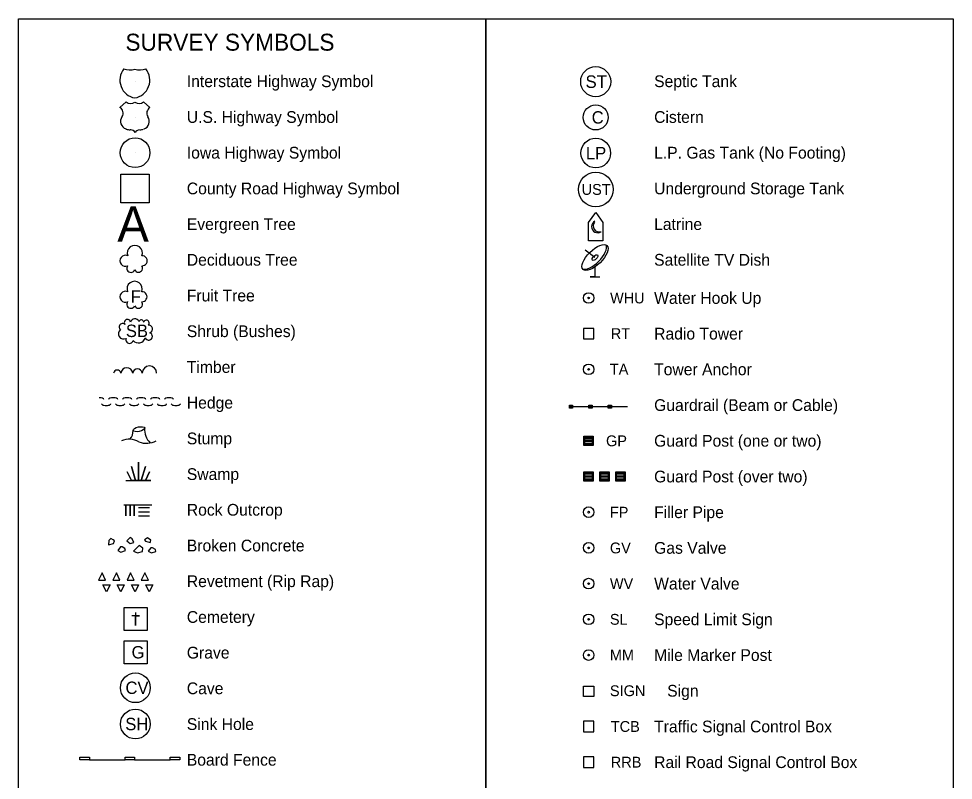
# Model space of a CAD drawing. Extents: x 6082259 to 6083454, y 5964102 to 5966092.
# Drawn here: x 6082259 to 6083454, y 5965119 to 5966092 of the extents above; entities that cross this region are included whole.
import ezdxf

# ---------------------------------------------------------------- set-up
doc = ezdxf.new("R2010")
doc.units = 0
for name, color, linetype in [('Default', 7, 'Continuous'), ('Level 20', 7, 'Continuous'), ('SurPropertyCells', 7, 'Continuous'), ('Text', 7, 'Continuous')]:
    doc.layers.add(name, color=color, linetype=linetype)

msp = doc.modelspace()

# ---------------------------------------------------------------- linework, layer by layer
at = {"layer": 'Default'}
for points in [[(6082259, 5966092.2), (6082856.5, 5966092.2), (6082856.5, 5964102.2), (6082259, 5964102.2)], [(6082856.5, 5966092.2), (6083454, 5966092.2), (6083454, 5964102.2), (6082856.5, 5964102.2)]]:
    msp.add_lwpolyline(points, close=True, dxfattribs=at)
at = {"layer": 'Level 20'}
for p, q in [((6082407.8, 5966012.2), (6082407.8, 5966012.2)), ((6082388.5, 5965978.8), (6082396.6, 5965986)), ((6082418.8, 5965985.9), (6082426.9, 5965978.7)), ((6082391, 5965966.7), (6082391.4, 5965967.3)), ((6082407.8, 5965966.5), (6082407.8, 5965966.5)), ((6082396.7, 5965951), (6082396, 5965951.3)), ((6082402.5, 5965950.1), (6082401.5, 5965950.1)), ((6082407.8, 5965920.9), (6082407.8, 5965920.9)), ((6082995.9, 5965786.9), (6082983.5, 5965796.2)), ((6082412.3, 5965467.3), (6082426.5, 5965467.3)), ((6082412.3, 5965462), (6082426.5, 5965462)), ((6082412.3, 5965456.6), (6082426.5, 5965456.6))]:
    msp.add_line(p, q, dxfattribs=at)
for points in [[(6082389.5, 5965893.5), (6082426, 5965893.5), (6082426, 5965857), (6082389.5, 5965857), (6082389.5, 5965893.5)], [(6082987.8, 5965808.3), (6082987.8, 5965831.8), (6082996.9, 5965844.5), (6083005.9, 5965831.8), (6083005.9, 5965808.3), (6082987.8, 5965808.3)], [(6082995.9, 5965774.5), (6082995.9, 5965762.1), (6082989.7, 5965762.1), (6083002.1, 5965762.1)], [(6082987.8, 5965682.8), (6082987.8, 5965682.8), (6082994.6, 5965682.8), (6082994.6, 5965696.4), (6082981, 5965696.4), (6082981, 5965682.8), (6082987.8, 5965682.8)], [(6082963.2, 5965594.3), (6082963.2, 5965598.4), (6082967.3, 5965598.4), (6082967.3, 5965594.3), (6082963.2, 5965594.3), (6082963.2, 5965595.7), (6082967.3, 5965595.7), (6082967.3, 5965597), (6082963.2, 5965597)], [(6082963.2, 5965596.4), (6083037.5, 5965596.4)], [(6082988, 5965594.3), (6082988, 5965598.4), (6082992.1, 5965598.4), (6082992.1, 5965594.3), (6082988, 5965594.3), (6082988, 5965595.7), (6082992.1, 5965595.7), (6082992.1, 5965597), (6082988, 5965597)], [(6083012.7, 5965594.3), (6083012.7, 5965598.4), (6083016.9, 5965598.4), (6083016.9, 5965594.3), (6083012.7, 5965594.3), (6083012.7, 5965595.7), (6083016.9, 5965595.7), (6083016.9, 5965597), (6083012.7, 5965597)], [(6082982.8, 5965547.7), (6082982.8, 5965557.6), (6082992.7, 5965557.6), (6082992.7, 5965547.7), (6082982.8, 5965547.7), (6082982.8, 5965549.7), (6082992.7, 5965549.7), (6082992.7, 5965551.7), (6082982.8, 5965551.7), (6082982.8, 5965553.7), (6082992.7, 5965553.7), (6082992.7, 5965555.6), (6082982.8, 5965555.6)], [(6082396, 5965502.1), (6082428.1, 5965502.1), (6082421, 5965502.1), (6082426.3, 5965512.8), (6082421, 5965502.1), (6082415.6, 5965502.1), (6082421, 5965520), (6082415.6, 5965502.1), (6082412.1, 5965502.1), (6082412.1, 5965525.3), (6082412.1, 5965502.1), (6082408.5, 5965502.1), (6082403.2, 5965520), (6082408.5, 5965502.1), (6082403.2, 5965502.1), (6082397.8, 5965512.8), (6082403.2, 5965502.1)], [(6082982.8, 5965502.1), (6082982.8, 5965512), (6082992.7, 5965512), (6082992.7, 5965502.1), (6082982.8, 5965502.1), (6082982.8, 5965504.1), (6082992.7, 5965504.1), (6082992.7, 5965506), (6082982.8, 5965506), (6082982.8, 5965508), (6082992.7, 5965508), (6082992.7, 5965510), (6082982.8, 5965510)], [(6083003.2, 5965502.1), (6083003.2, 5965512), (6083013.1, 5965512), (6083013.1, 5965502.1), (6083003.2, 5965502.1), (6083003.2, 5965504.1), (6083013.1, 5965504.1), (6083013.1, 5965506), (6083003.2, 5965506), (6083003.2, 5965508), (6083013.1, 5965508), (6083013.1, 5965510), (6083003.2, 5965510)], [(6083023.5, 5965502.1), (6083023.5, 5965512), (6083033.4, 5965512), (6083033.4, 5965502.1), (6083023.5, 5965502.1), (6083023.5, 5965504.1), (6083033.4, 5965504.1), (6083033.4, 5965506), (6083023.5, 5965506), (6083023.5, 5965508), (6083033.4, 5965508), (6083033.4, 5965510), (6083023.5, 5965510)], [(6082393.5, 5965470.9), (6082396.2, 5965470.9), (6082396.2, 5965456.6), (6082396.2, 5965470.9), (6082401.6, 5965470.9), (6082401.6, 5965456.6), (6082401.6, 5965470.9), (6082406.9, 5965470.9), (6082406.9, 5965456.6), (6082406.9, 5965470.9), (6082429.2, 5965470.9)], [(6082361, 5965374.6), (6082370.2, 5965374.6), (6082365.6, 5965383.8), (6082361, 5965374.6)], [(6082379.3, 5965374.6), (6082388.4, 5965374.6), (6082383.9, 5965383.8), (6082379.3, 5965374.6)], [(6082397.6, 5965374.6), (6082406.7, 5965374.6), (6082402.1, 5965383.8), (6082397.6, 5965374.6)], [(6082415.8, 5965374.6), (6082424.9, 5965374.6), (6082420.4, 5965383.8), (6082415.8, 5965374.6)], [(6082366.7, 5965368.6), (6082375.8, 5965368.6), (6082371.2, 5965359.5), (6082366.7, 5965368.6)], [(6082384.9, 5965368.6), (6082394.1, 5965368.6), (6082389.5, 5965359.5), (6082384.9, 5965368.6)], [(6082403.2, 5965368.6), (6082412.3, 5965368.6), (6082407.8, 5965359.5), (6082403.2, 5965368.6)], [(6082421.5, 5965368.6), (6082430.6, 5965368.6), (6082426, 5965359.5), (6082421.5, 5965368.6)], [(6082393.8, 5965310.2), (6082393.8, 5965339.7), (6082423.4, 5965339.7), (6082423.4, 5965310.2), (6082393.8, 5965310.2)], [(6082408.6, 5965333.3), (6082408.6, 5965316.6), (6082408.6, 5965328.9), (6082413.5, 5965328.9), (6082403.7, 5965328.9)], [(6082987.8, 5965180.8), (6082987.8, 5965180.8), (6082994.6, 5965180.8), (6082994.6, 5965194.3), (6082981, 5965194.3), (6082981, 5965180.8), (6082987.8, 5965180.8)], [(6082349.4, 5965145), (6082395, 5965145)], [(6082407.2, 5965145), (6082452.8, 5965145)], [(6082464.9, 5965145), (6082464.9, 5965145)], [(6082987.8, 5965135.1), (6082987.8, 5965135.1), (6082994.6, 5965135.1), (6082994.6, 5965148.7), (6082981, 5965148.7), (6082981, 5965135.1), (6082987.8, 5965135.1)]]:
    msp.add_lwpolyline(points, dxfattribs=at)
for points in [[(6082981.8, 5965546.7), (6082981.8, 5965558.6), (6082993.7, 5965558.6), (6082993.7, 5965546.7)], [(6082981.8, 5965501.1), (6082981.8, 5965513), (6082993.7, 5965513), (6082993.7, 5965501.1)], [(6083002.2, 5965501.1), (6083002.2, 5965513), (6083014.1, 5965513), (6083014.1, 5965501.1)], [(6083022.5, 5965501.1), (6083022.5, 5965513), (6083034.4, 5965513), (6083034.4, 5965501.1)], [(6082401.7, 5965429), (6082397.3, 5965424.9), (6082401.5, 5965421.3), (6082406.4, 5965422.8), (6082404.3, 5965427.2)], [(6082423.7, 5965428.6), (6082419.9, 5965426.3), (6082421.1, 5965424.2), (6082427.1, 5965422.6), (6082427.9, 5965425.5)], [(6082376.8, 5965427.8), (6082374.2, 5965425.4), (6082373.7, 5965419.7), (6082380.2, 5965421.3), (6082381.5, 5965424.9), (6082379.7, 5965426.2)], [(6082389.2, 5965417.2), (6082385.6, 5965412.5), (6082389.8, 5965410.4), (6082395.5, 5965412.3), (6082394.9, 5965415.1), (6082391.3, 5965417.2)], [(6082413.2, 5965419), (6082406, 5965411.8), (6082410.9, 5965409.4), (6082417.4, 5965411.3), (6082417.6, 5965415.4)], [(6082428.2, 5965416), (6082424.6, 5965411.4), (6082428.7, 5965409.3), (6082434.4, 5965411.1), (6082433.9, 5965413.9), (6082430.3, 5965416)], [(6082393.7, 5965267.5), (6082393.7, 5965297.2), (6082423.5, 5965297.2), (6082423.5, 5965267.5)], [(6082981, 5965225.7), (6082981, 5965239.2), (6082994.6, 5965239.2), (6082994.6, 5965225.7)], [(6082337.2, 5965145), (6082337.2, 5965148.4), (6082349.4, 5965148.4), (6082349.4, 5965145)], [(6082395, 5965145), (6082395, 5965148.4), (6082407.2, 5965148.4), (6082407.2, 5965145)], [(6082452.8, 5965145), (6082452.8, 5965148.4), (6082464.9, 5965148.4), (6082464.9, 5965145)]]:
    msp.add_lwpolyline(points, close=True, dxfattribs=at)
for centre, radius in [((6082996.8, 5965966), 16), ((6082407.8, 5965920.9), 19), ((6082996.9, 5965920.5), 19), ((6082996.9, 5965873.9), 22.2), ((6082987.8, 5965735.2), 6.79), ((6082987.8, 5965735.2), 1.13), ((6082987.8, 5965644), 6.79), ((6082987.8, 5965644), 1.13), ((6082987.8, 5965461.4), 6.79), ((6082987.8, 5965461.4), 1.13), ((6082987.8, 5965415.8), 6.79), ((6082987.8, 5965415.8), 1.13), ((6082987.8, 5965370.1), 6.79), ((6082987.8, 5965370.1), 1.13), ((6082987.8, 5965324.5), 6.79), ((6082987.8, 5965324.5), 1.13), ((6082987.8, 5965278.8), 6.79), ((6082987.8, 5965278.8), 1.13), ((6082408.2, 5965237), 19), ((6082408.2, 5965190.7), 19)]:
    msp.add_circle(centre, radius, dxfattribs=at)
for centre, radius, start, end in [((6082411.4, 5966013.6), 23, 141.2897, 260.377), ((6082401.1, 5966050), 23.3, 250.8344, 286.0898), ((6082414, 5966050), 23.3, 253.9102, 289.1613), ((6082403.7, 5966013.6), 23, 279.623, 38.7204), ((6082414, 5966050), 23.3, 289.1818, 289.185), ((6082384.1, 5965971.6), 8.46, 328.1178, 58.4185), ((6082402.4, 5965992.1), 8.46, 226.652, 308.6604), ((6082413, 5965992.1), 8.46, 230.5703, 313.348), ((6082431.3, 5965971.5), 8.46, 121.5815, 211.8822), ((6082399.6, 5965961), 10.3, 145.8972, 250.3585), ((6082415.8, 5965960.9), 10.3, 289.6415, 34.1028), ((6082403.5, 5965974.1), 24.1, 253.4797, 265.7777), ((6082402.1, 5965943), 7.07, 33.6844, 87.4407), ((6082413.9, 5965942.9), 7.07, 95.8567, 146.3156), ((6082411.9, 5965974.1), 24.1, 274.6642, 286.5203), ((6082999.3, 5965826.4), 7.87, 116.2289, 304.7925), ((6083001.5, 5965827.5), 7.91, 142.8907, 286.2253), ((6082407.5, 5965792.7), 9.75, 338.2051, 201.7949), ((6082395.5, 5965782.8), 6.97, 65.4824, 294.5175), ((6082417, 5965782.8), 6.36, 265.9982, 94.0018), ((6082402.6, 5965773.2), 5.31, 142.7501, 335.3223), ((6082412.2, 5965773.4), 5.3, 206.5242, 35.4033), ((6082407.3, 5965746.8), 9.75, 338.2051, 201.7949), ((6082395.4, 5965736.8), 6.97, 65.4824, 294.5175), ((6082416.8, 5965736.8), 6.36, 265.9982, 94.0018), ((6082402.5, 5965727.3), 5.31, 142.7501, 335.3223), ((6082412.1, 5965727.4), 5.3, 206.5242, 35.4033), ((6082398.1, 5965703.7), 4.12, 10.5948, 214.3611), ((6082407.6, 5965703.1), 5.57, 22.6036, 165.7836), ((6082415.7, 5965704.1), 3.15, 0.4605, 158.7839), ((6082422.3, 5965703.3), 3.57, 311.3936, 166.4114), ((6082393.2, 5965689.4), 6.62, 125.8289, 299.2848), ((6082391.7, 5965698.3), 4.32, 45.3455, 236.8073), ((6082425, 5965695.5), 5.15, 290.9039, 94.3687), ((6082400.8, 5965681.8), 4.68, 157.0258, 349.7602), ((6082412.2, 5965686.7), 8.99, 220.0183, 343.6977), ((6082425.2, 5965686.2), 4.79, 204.8294, 69.8871), ((6082397.2, 5965638.4), 7.66, 5.6097, 174.3903), ((6082410.9, 5965638.4), 6.15, 6.8184, 173.1816), ((6082426.2, 5965639.2), 9.15, 0, 180), ((6082385, 5965638.5), 4.63, 8.8069, 171.1931), ((6082388.6, 5965565.5), 16.7, 319.4836, 1.8241), ((6082444, 5965567.1), 24, 175.4776, 225.2691), ((6082400.1, 5965530.5), 24.2, 58.6739, 113.6979), ((6082422.1, 5965578.6), 29, 251.1942, 296.4339)]:
    msp.add_arc(centre, radius, start, end, dxfattribs=at)
for centre, major_axis, ratio in [((6082995.9, 5965786.9), (-15.3, -15.3), 0.428571), ((6082995.9, 5965786.9), (-3.28, -3.28), 0.5), ((6082412.7, 5965567.5), (-7.43, -1.49), 0.385758)]:
    msp.add_ellipse(centre, major_axis=major_axis, ratio=ratio, dxfattribs=at)
for centre, major_axis, ratio, start_param, end_param in [((6082994.1, 5965788.6), (-15.3, -15.3), 0.428571, 0.159141, 2.993624), ((6082362.1, 5965605.4), (5.94, 0), 0.4, 0, 1.570796), ((6082379.9, 5965605.4), (-5.94, 0), 0.4, 4.712389, 6.283185), ((6082379.9, 5965605.4), (5.94, 0), 0.4, 0, 1.570796), ((6082397.7, 5965605.4), (-5.94, 0), 0.4, 4.712389, 6.283185), ((6082397.7, 5965605.4), (5.94, 0), 0.4, 0, 1.570796), ((6082415.5, 5965605.4), (-5.94, 0), 0.4, 4.712389, 6.283185), ((6082415.5, 5965605.4), (5.94, 0), 0.4, 0, 1.570796), ((6082433.4, 5965605.4), (-5.94, 0), 0.4, 4.712389, 6.283185), ((6082433.4, 5965605.4), (5.94, 0), 0.4, 0, 1.570796), ((6082451.2, 5965605.4), (-5.94, 0), 0.4, 4.712389, 6.283185), ((6082451.2, 5965605.4), (5.94, 0), 0.4, 0, 1.570796), ((6082371, 5965600.1), (-5.94, 0), 0.4, 0, 3.141593), ((6082388.8, 5965600.1), (-5.94, 0), 0.4, 0, 3.141593), ((6082406.6, 5965600.1), (-5.94, 0), 0.4, 0, 3.141593), ((6082424.5, 5965600.1), (-5.94, 0), 0.4, 0, 3.141593), ((6082442.3, 5965600.1), (-5.94, 0), 0.4, 0, 3.141593), ((6082460.1, 5965600.1), (-5.94, 0), 0.4, 0, 3.141593)]:
    msp.add_ellipse(centre, major_axis=major_axis, ratio=ratio, start_param=start_param, end_param=end_param, dxfattribs=at)
at = {"layer": 'SurPropertyCells'}
msp.add_circle((6082996.8, 5966011.7), 19.2, dxfattribs=at)

# ---------------------------------------------------------------- texts
at = {"layer": 'Level 20'}
for s, height, p in [('C', 15.8, (6082991.7, 5965958.1)), ('LP', 15.85, (6082984.3, 5965912.5)), ('UST', 13.87, (6082978.8, 5965867)), ('A', 45.3, (6082385.1, 5965807)), ('F', 15.8, (6082402.3, 5965729.3)), ('WHU', 13.82, (6083015.2, 5965728.3)), ('SB', 15.85, (6082396.1, 5965685.3)), ('RT', 13.87, (6083016.1, 5965682.7)), ('TA', 13.93, (6083014.8, 5965637.2)), ('GP', 13.87, (6083010, 5965545.7)), ('FP', 13.82, (6083015, 5965454.5)), ('GV', 13.82, (6083015, 5965408.8)), ('WV', 13.82, (6083015, 5965363.2)), ('SL', 13.82, (6083015, 5965317.6)), ('G', 15.8, (6082403.4, 5965274.5)), ('MM', 13.82, (6083015, 5965271.9)), ('CV', 15.85, (6082395.6, 5965229.1)), ('Cave', 15, (6082474, 5965228.8)), ('SIGN', 13.87, (6083015, 5965226.3)), ('Sign', 15, (6083088.2, 5965225.7)), ('SH', 15.85, (6082395.3, 5965182.8)), ('TCB', 13.87, (6083016.1, 5965180.6)), ('RRB', 13.87, (6083016.1, 5965135))]:
    msp.add_text(s, height=height, dxfattribs=at).set_placement(p)
at = {"layer": 'SurPropertyCells'}
msp.add_text('ST', height=15.99, dxfattribs=at).set_placement((6082983.8, 5966003.7))
at = {"layer": 'Text'}
for s, height, p in [('SURVEY SYMBOLS', 21.667, (6082395.5, 5966051.3)), ('Interstate Highway Symbol', 15, (6082474, 5966004.7)), ('Septic Tank', 15, (6083071.5, 5966004.7)), ('U.S. Highway Symbol', 15, (6082474, 5965959)), ('Cistern', 15, (6083071.5, 5965959)), ('Iowa Highway Symbol', 15, (6082474, 5965913.4)), ('L.P. Gas Tank (No Footing)', 15, (6083071.5, 5965913.4)), ('County Road Highway Symbol', 15, (6082474, 5965867.7)), ('Underground Storage Tank', 15, (6083071.5, 5965867.7)), ('Evergreen Tree', 15, (6082474, 5965822.1)), ('Latrine', 15, (6083071.5, 5965822.1)), ('Deciduous Tree', 15, (6082474, 5965776.5)), ('Satellite TV Dish', 15, (6083071.5, 5965776.5)), ('Fruit Tree', 15, (6082474, 5965730.8)), ('Water Hook Up', 15, (6083071.5, 5965727.7)), ('Shrub (Bushes)', 15, (6082474, 5965685.2)), ('Radio Tower', 15, (6083071.5, 5965682.1)), ('Timber', 15, (6082474, 5965639.5)), ('Tower Anchor', 15, (6083071.5, 5965636.5)), ('Hedge', 15, (6082474, 5965593.9)), ('Guardrail (Beam or Cable)', 15, (6083071.5, 5965590.8)), ('Stump', 15, (6082474, 5965548.2)), ('Guard Post (one or two)', 15, (6083071.5, 5965545.2)), ('Swamp', 15, (6082474, 5965502.6)), ('Guard Post (over two)', 15, (6083071.5, 5965499.5)), ('Rock Outcrop', 15, (6082474, 5965457)), ('Filler Pipe', 15, (6083071.5, 5965453.9)), ('Broken Concrete', 15, (6082474, 5965411.3)), ('Gas Valve', 15, (6083071.5, 5965408.3)), ('Revetment (Rip Rap)', 15, (6082474, 5965365.7)), ('Water Valve', 15, (6083071.5, 5965362.6)), ('Cemetery', 15, (6082474, 5965320)), ('Speed Limit Sign', 15, (6083071.5, 5965317)), ('Grave', 15, (6082474, 5965274.4)), ('Mile Marker Post', 15, (6083071.5, 5965271.3)), ('Sink Hole', 15, (6082474, 5965183.1)), ('Traffic Signal Control Box', 15, (6083071.5, 5965180)), ('Board Fence', 15, (6082474, 5965137.5)), ('Rail Road Signal Control Box', 15, (6083071.5, 5965134.4))]:
    msp.add_text(s, height=height, dxfattribs=at).set_placement(p)

doc.saveas('drawing.dxf')
